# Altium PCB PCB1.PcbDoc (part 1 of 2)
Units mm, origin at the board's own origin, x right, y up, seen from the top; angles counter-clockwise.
Board outline 100 x 100 mm, 2 copper layers (Top Layer, Bottom Layer); 114 components, 82 nets, 496 pads, 121 vias.
Unrouted connection lines stored in the file: 6.
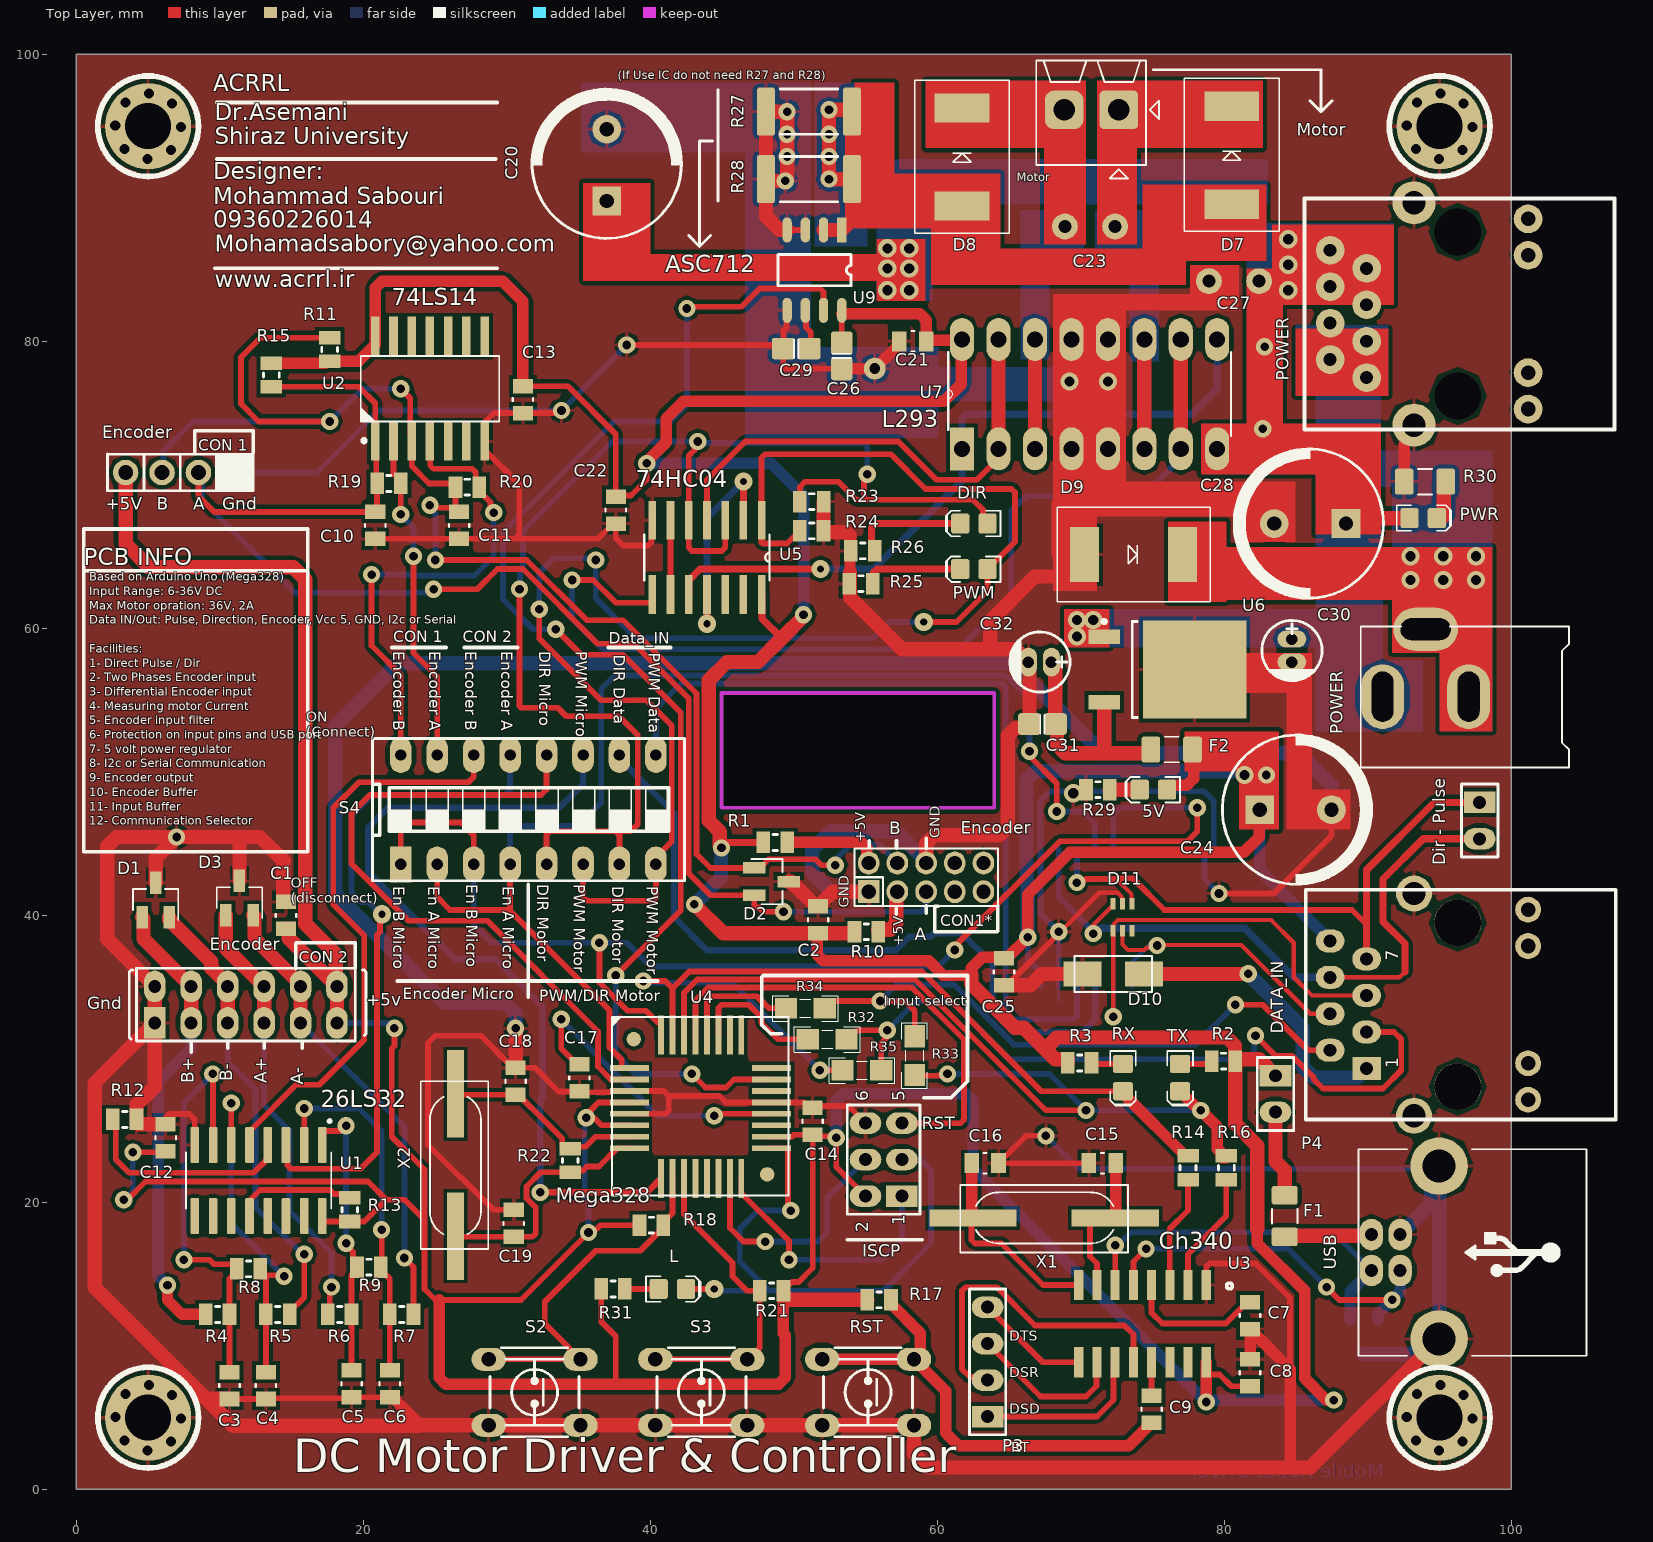
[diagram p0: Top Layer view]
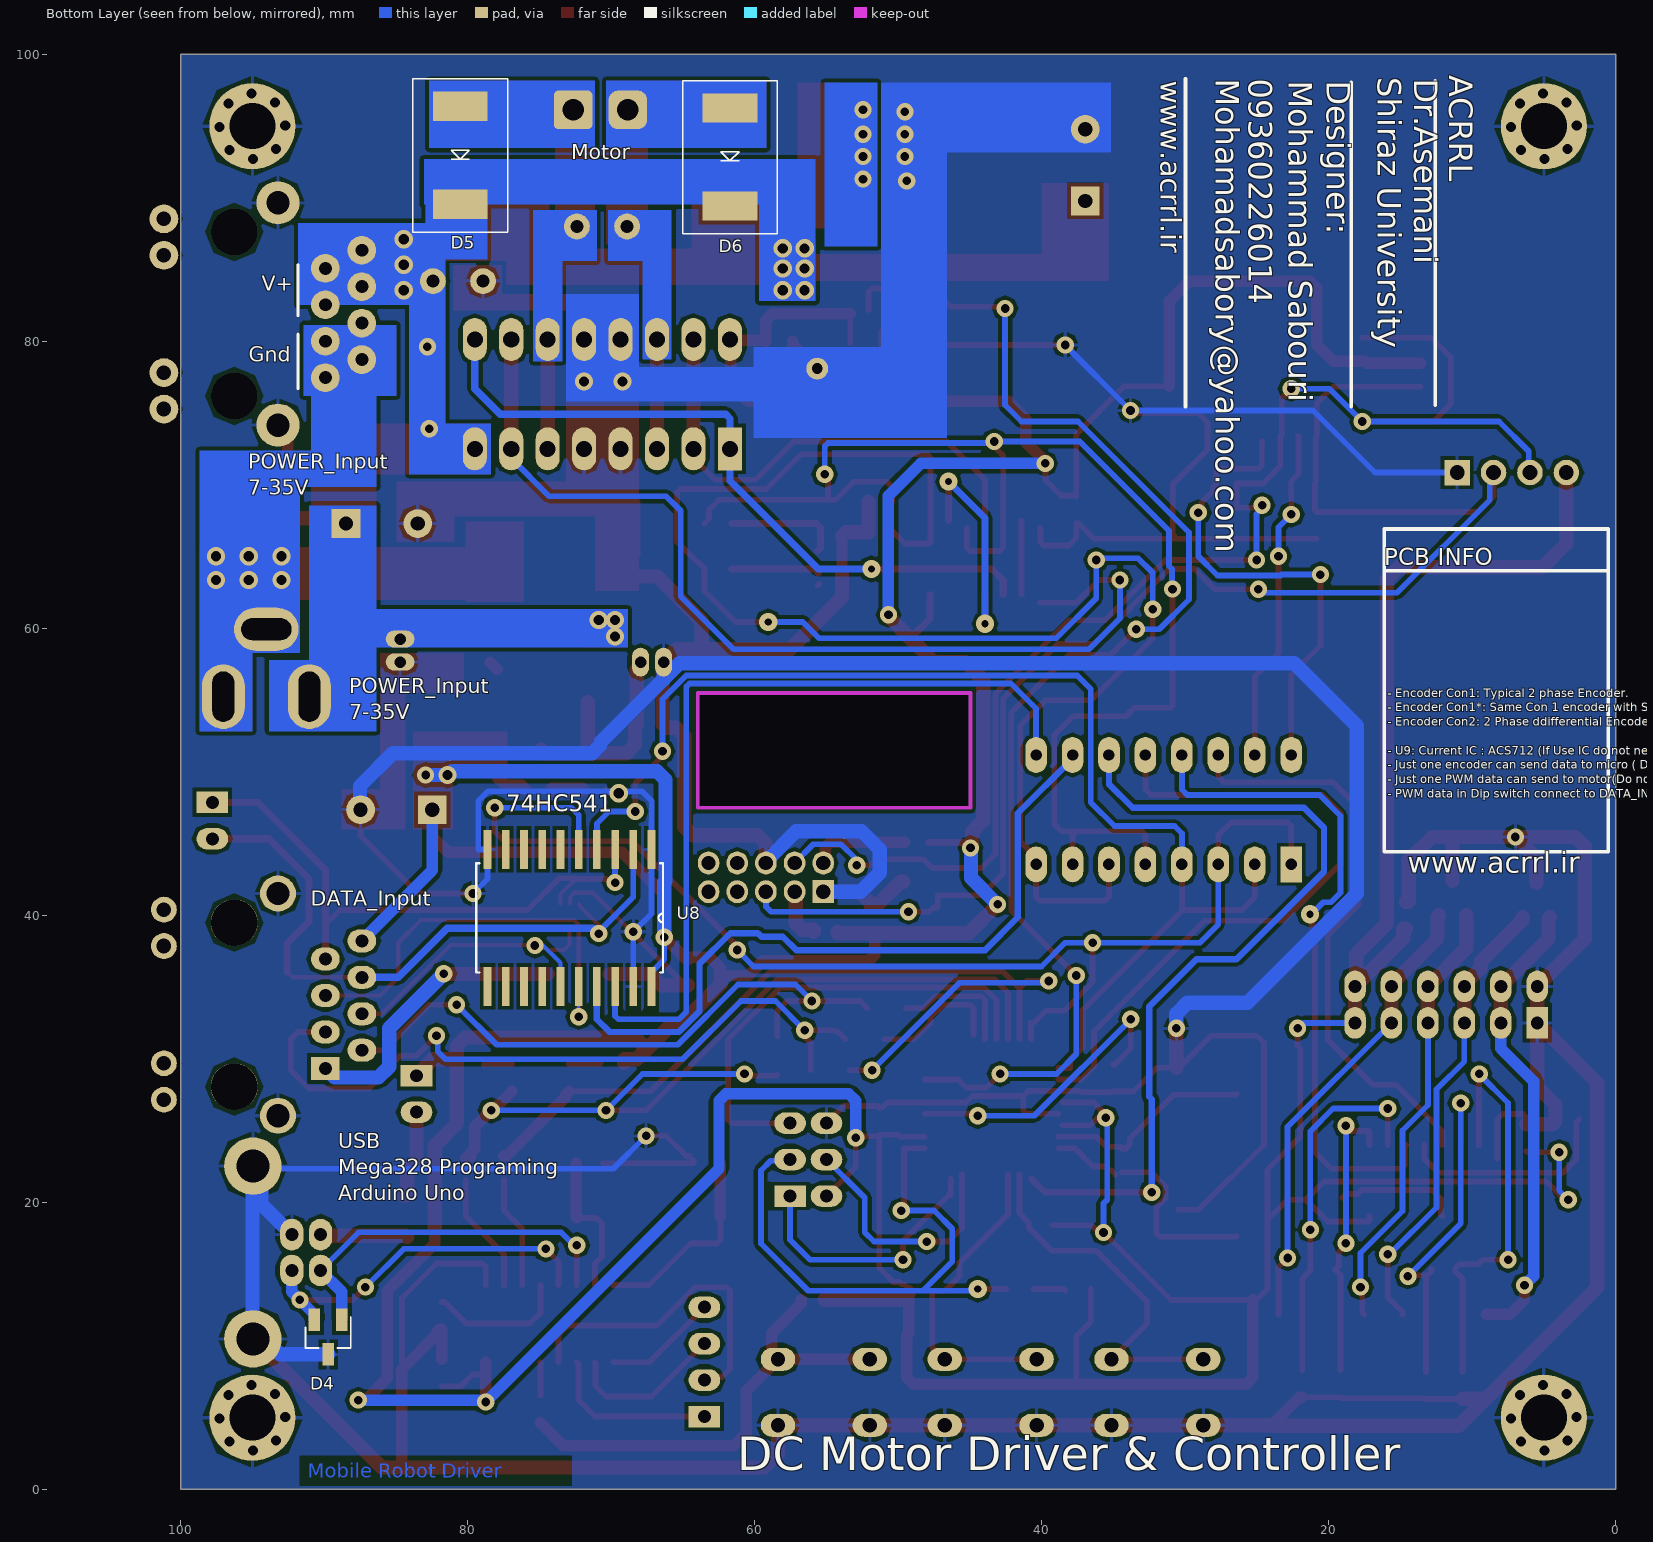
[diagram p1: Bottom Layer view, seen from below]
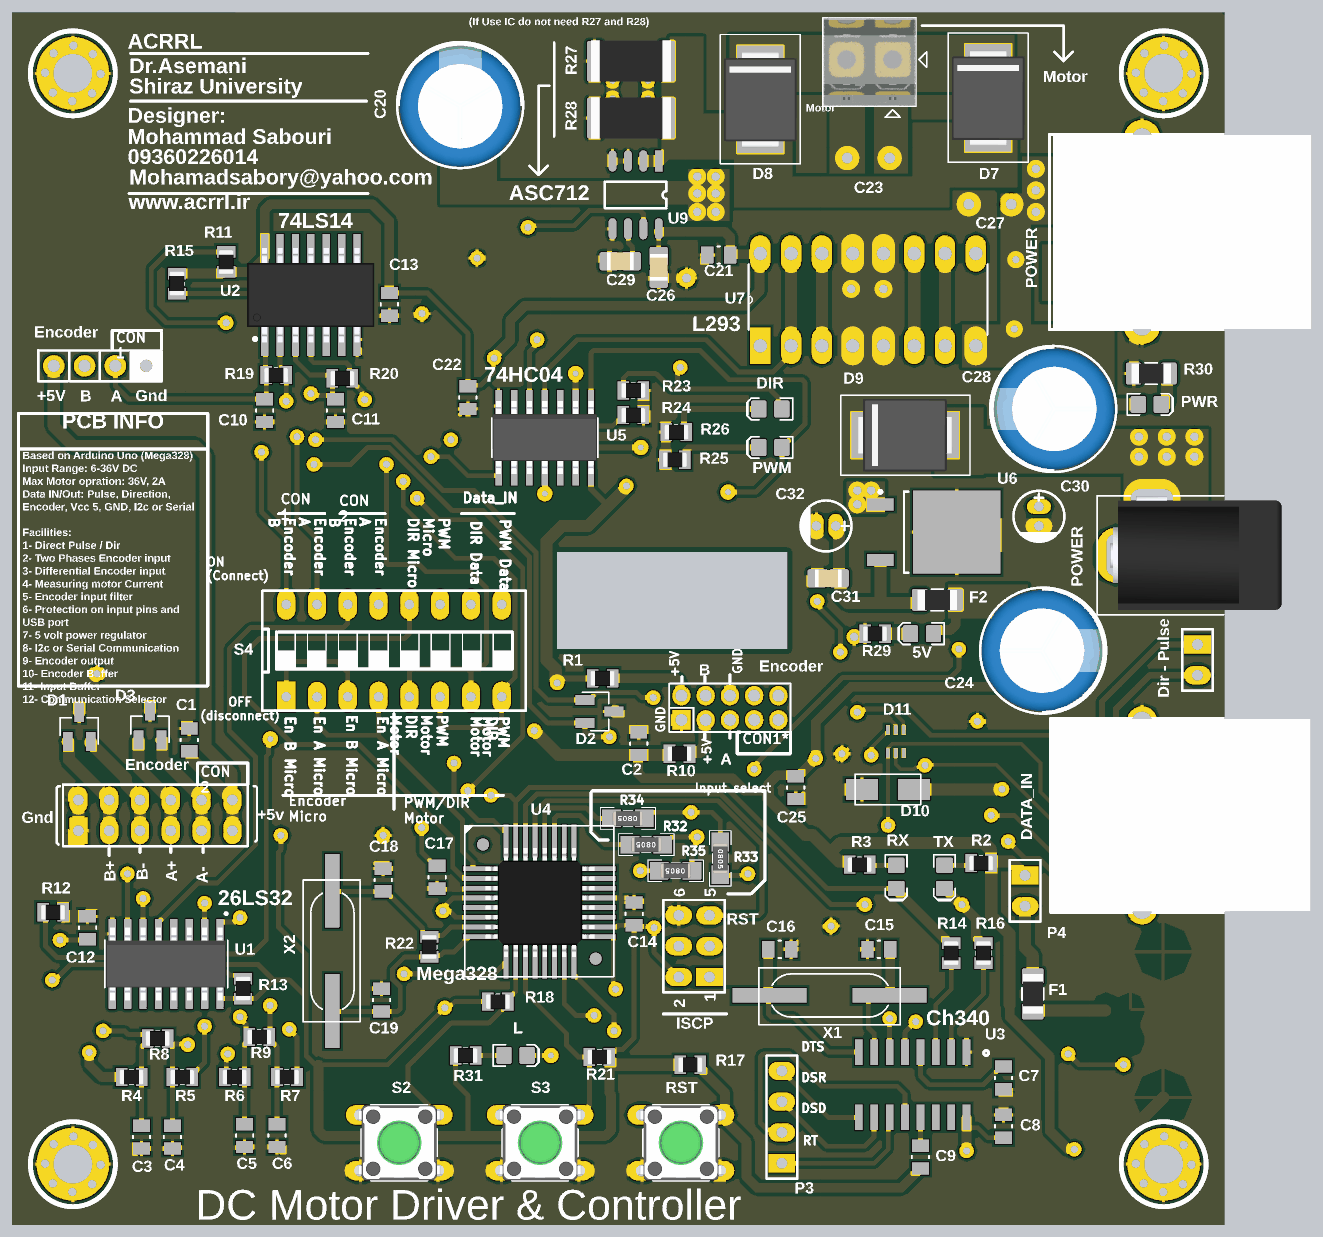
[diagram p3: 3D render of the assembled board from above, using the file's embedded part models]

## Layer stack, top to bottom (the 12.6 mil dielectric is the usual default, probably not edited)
Top Solder: solder mask 0.0102, Solder Resist, Dk 3.5
Top Layer: signal copper 0.0356
Dielectric 1: dielectric 0.32, FR-4, Dk 4.8
Bottom Layer: signal copper 0.0356
Bottom Solder: solder mask 0.0102, Solder Resist, Dk 3.5

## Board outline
0,0 0,100.005 100,100.005 100,0
cut-out: 44.958,55.498 63.958,55.498 63.958,47.498 44.958,47.498

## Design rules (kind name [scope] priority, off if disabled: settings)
Clearance Clearance_3 [InNamedPolygon('GND_L02_P-001')] p1: gap=0.254 ignorepadtopadclearanceinfootprint=FALSE
Clearance Clearance_2 [InNamedPolygon('GND_L02_P-001')] p2: gap=0.254 ignorepadtopadclearanceinfootprint=FALSE
Clearance Clearance_1 [InNamedPolygon('GND_L02_P-001')] p3: gap=0.15 ignorepadtopadclearanceinfootprint=FALSE
Clearance [All] p4: gap=0.15 ignorepadtopadclearanceinfootprint=FALSE
PolygonConnect [All] p1: connectstyle=Relief reliefconductorwidth=0.254 reliefentries=4 polygonreliefangle="90 Angle" airgapwidth=0.254
RoutingVias [All] p1: holewidth=0.8 width=1 viastyle="Through Hole" minholewidth=0.5 minwidth=0.5 maxholewidth=1 maxwidth=1.65
SolderMaskExpansion [All] p1: expansion=0.102 istentingtop=FALSE
Width [All] p1: maxlimit=1 minlimit=0.2 preferedwidth=0.8
30 further rules are at their usual default settings.

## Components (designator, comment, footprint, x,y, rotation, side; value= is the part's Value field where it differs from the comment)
5V "Red" LED-0805-K 75.057,48.768 r180 top
C1 "470nF 50V" 0805 14.605,40.005 r90 top value=470nF
C2 "100nF" 0805 51.689,39.7 r90 top value=470nF
C3 "22pF" 0805 10.668,7.239 r270 top value=470nF
C4 "22pF" 0805 13.208,7.239 r270 top value=470nF
C5 "22pF" 0805 19.177,7.366 r270 top value=470nF
C6 "22pF" 0805 21.844,7.366 r270 top value=470nF
C7 "100nF" 0805 81.788,12.116 r270 top value=470nF
C8 "100nF" 0805 81.788,8.128 r90 top value=470nF
C9 "100nf" 0805 74.93,5.588 r270 top value=470nF
C10 "1uF" 0805 20.828,67.183 r90 top value=470nF
C11 "1uF" 0805 26.67,67.183 r90 top value=470nF
C12 "22pF" 0805 6.223,24.511 r90 top value=470nF
C13 "100nF" 0805 31.115,75.946 r270 top value=470nF
C14 "1uF" 0805 51.308,25.654 r90 top value=470nF
C15 "22pF" 0805 71.501,22.733 r0 top value=470nF
C16 "22pF" 0805 63.322,22.733 r180 top value=470nF
C17 "100nf" 0805 35.052,28.677 r90 top value=470nF
C18 "22pF" 0805 30.607,28.448 r90 top value=470nF
C19 "22pF" 0805 30.48,18.542 r270 top value=470nF
C20 "1000u" "Cap electrolitic radial 10x16-5" 36.957,92.289 r90 top
C21 "470nF 50V" 0805 58.293,80.01 r180 top value=470nF
C22 "22nF 50V" 0805 37.592,68.25 r270 top value=470nF
C23 "100nF" "CAP Ceramic 3.5mm" 72.39,88.011 r180 top
C24 "1000u" "Cap electrolitic radial 10x16-5" 84.963,47.371 r0 top
C25 "470nF 50V" 0805 64.643,36.068 r90 top value=470nF
C26 "approved sub OK" CAPC2012X135N 53.34,78.994 r90 top value=0.1µ
C27 "330pF" "CAP Ceramic 3.5mm" 78.923,84.201 r0 top
C28 "1000u" "Cap electrolitic radial 10x16-5" 85.979,67.31 r180 top
C29 "approved sub OK" CAPC2012X135N 50.165,79.502 r180 top value=1n8
C30 "0.1uF" "cap 00"#1 84.709,58.458 r90 top
C31 "approved sub OK" CAPC2012X135N 67.321,53.34 r180 top value=0.1µ
C32 "0.3uF" "cap 00"#2 67.145,57.658 r0 top
D1 "SM712" PCBComponent_1#1 4.577,39.878 r90 top
D2 "SM712" PCBComponent_1#2 47.244,41.407 r0 top
D3 "SM712" PCBComponent_1#1 10.414,40.005 r90 top
D4 "SM712" PCBComponent_1#2 90.673,11.811 r270 bottom
D5 "SMCJ120CA" DIODE-SMC 80.518,96.893 r90 bottom
D6 "SMCJ120CA" DIODE-SMC 61.722,96.766 r90 bottom
D7 "SMCJ120CA" DIODE-SMC 80.518,89.059 r270 top
D8 "SMCJ120CA" DIODE-SMC 61.722,88.932 r270 top
D9 "SMCJ120CA" DIODE-SMC 69.755,65.151 r180 top
D10 "Diode 1N5819" DO-214AC 72.248,35.918 r0 top
D11 "SMF05C.TCT" SC70-6 72.898,39.878 r180 top
DATA_IN "215877-1 RJ45" HR911105A#1 89.916,29.337 r0 top
DIR "Green" LED-0805-K 62.547,67.31 r180 top
"Dir - Pulse" "Header 2" HDR1X2 97.79,47.879 r270 top (schematic designator "D / P")
Encoder "Encoder" HDR2X6 5.461,32.512 r0 top
Encoder "Encoder motor_AB" hhh 55.214,41.656 r0 top
Encoder "Encoder_Motor" HEADER-1X4 11.049,70.866 r270 top
F1 "Slow-blow" RESC3216X70N 84.201,19.05 r270 top value=500mA
F2 "Slow-blow" RESC3216X70N 76.327,51.562 r0 top value=2A
ISCP "ISP" HDR2X3 57.531,20.447 r90 top
L "L" LED-0805-K 41.529,13.97 r0 top
Motor "Stackable ScrewTerm" 2P_PCB_ScrewTerm_90S_3.81MM 72.644,96.139 r90 top value="2 position"
P3 "Header 4" HDR1X4 63.5,5.08 r90 top
P4 "Header 2" HDR1X2 83.566,28.829 r270 top
POWER "CONN_PWR_JACK_2.1x5.5mm" CONN_PWR_JACK_2.1x5.5mm 104.728,55.245 r270 top value="2.1mm ID, 5.5mm OD"
POWER "215877-1 RJ45" HR911105A#2 96.266,81.915 r270 top
PWM "Green" LED-0805-K 62.547,64.135 r180 top
PWR "Red" LED-0805-K 93.853,67.691 r0 top
R1 "330" "RES 0805 (2012X06L)" 49.529,45.085 r180 top
R2 "1K" "RES 0805 (2012X06L)" 80.771,29.845 r180 top
R3 "1K" "RES 0805 (2012X06L)" 69.089,29.718 r0 top
R4 "1K" "RES 0805 (2012X06L)" 9.017,12.192 r0 top
R5 "1K" "RES 0805 (2012X06L)" 14.859,12.192 r180 top
R6 "1K" "RES 0805 (2012X06L)" 17.527,12.192 r0 top
R7 "1K" "RES 0805 (2012X06L)" 21.845,12.192 r0 top
R8 "120" "RES 0805 (2012X06L)" 12.826,15.367 r180 top
R9 "120" "RES 0805 (2012X06L)" 21.209,15.494 r180 top
R10 "120" "RES 0805 (2012X06L)" 55.879,38.862 r180 top
R11 "10K" "RES 0805 (2012X06L)" 17.653,80.263 r270 top
R12 "R0" "RES 0805 (2012X06L)" 4.19,25.781 r180 top
R13 "R0" "RES 0805 (2012X06L)" 19.05,18.669 r90 top
R14 "1K" "RES 0805 (2012X06L)" 77.47,23.241 r270 top
R15 "10K" "RES 0805 (2012X06L)" 13.589,76.835 r90 top
R16 "1K" "RES 0805 (2012X06L)" 80.137,23.241 r270 top
R17 "10K" "RES 0805 (2012X06L)" 55.118,13.208 r0 top
R18 "10K" "RES 0805 (2012X06L)" 39.243,18.415 r0 top
R19 "10K" "RES 0805 (2012X06L)" 20.955,70.104 r0 top
R20 "10K" "RES 0805 (2012X06L)" 26.416,69.85 r0 top
R21 "10K" "RES 0805 (2012X06L)" 49.275,13.843 r180 top
R22 "1M" "RES 0805 (2012X06L)" 34.417,23.748 r270 top
R23 "10K" "RES 0805 (2012X06L)" 50.42,68.834 r0 top
R24 "10K" "RES 0805 (2012X06L)" 50.419,66.802 r0 top
R25 "330" "RES 0805 (2012X06L)" 55.499,63.119 r180 top
R26 "330" "RES 0805 (2012X06L)" 55.626,65.405 r180 top
R27 "Thick Film" RESC6332X70N 51.054,96.012 r180 top value=R330
R28 "Thick Film" RESC6332X70N 51.054,91.313 r180 top value=R330
R29 "330" "RES 0805 (2012X06L)" 70.359,48.768 r0 top
R30 "Thin Film" RESC3216X70N 93.98,70.231 r180 top value=4.7K
R31 "1K" "RES 0805 (2012X06L)" 36.577,13.97 r0 top
R32 "0" RESC3413X04N 52.324,31.369 r180 top
R33 "0" RESC3413X04N 58.42,30.226 r270 top
R34 "0" RESC3413X04N 50.8,33.528 r180 top
R35 "0" RESC3413X04N 54.737,29.21 r180 top
RST "Switch PB 4Pin" SW_PB_THT_4PIN_SPDT_6X6X7 55.172,6.769 r180 top
RX "RX" LED-0805-K 72.936,28.702 r270 top
S2 "Switch PB 4Pin" SW_PB_THT_4PIN_SPDT_6X6X7 31.931,6.769 r180 top
S3 "Switch PB 4Pin" SW_PB_THT_4PIN_SPDT_6X6X7 43.552,6.769 r180 top
S4 "DIP8" "DIP Switch x8" 22.606,43.561 r0 top
TX "TX" LED-0805-K 76.915,28.702 r270 top
U1 "AM26LS32ACD" SOIC127P600X175-16N 12.7,21.525 r270 top
U2 "SN74LS14DR" SOIC127P780X200-14N 24.638,76.708 r90 top
U3 "CH340G" CH340G 74.295,11.557 r180 top
U4 "ATMEGA328" QFP32 38.842,29.371 r0 top
U5 "74HC04D,653" SOIC127P600X175-14N 43.942,64.948 r270 top
U6 "L7805CD2T-TR" TO252-3M 76.028,57.144 r180 top
U7 "L293N" DIP254P762X508-16 79.502,80.137 r90 top
U8 "74HC541D" SOIC127P1032X265-20N 72.898,39.827 r270 bottom
U9 "ACS712" SOIC8 53.34,87.769 r270 top
USB "USB-B" USB_TypeB_Tyco 105.241,16.51 r180 top
X1 "12MC" XTAL-RU49/4 72.39,18.923 r180 top
X2 "16MC" XTAL-RU49/4 26.416,17.653 r90 top

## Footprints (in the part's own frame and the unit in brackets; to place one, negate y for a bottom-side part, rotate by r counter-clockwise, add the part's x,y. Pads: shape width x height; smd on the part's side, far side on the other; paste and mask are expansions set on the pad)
2P_PCB_ScrewTerm_90S_3.81MM [mm] "TERM BLOCK 2POS SIDE ENT STACKABLE 3.81MM"
  rrect50% 2.7x2.7 hole 1.5: 2(0,3.81)
  rrect25% 2.7x2.7 hole 1.5: F(0,0)
  silkscreen extent -4.78,-2.79 3.45,5.75, body extent -3.85,-1.91 3.45,5.71, height 8.5
0805 [mil]
  rect 40x55 smd: 1(-37,0) 2(37,0)
  silkscreen extent -4,-28 4,28, body extent -47,-28 47,28, height 24
"cap 00"#1 [mm]
  oval 1.2x2 hole 0.8: 1(0.8,0) F(-0.8,0)
  silkscreen extent -2.1,-2.1 2.1,2.1
"cap 00"#2 [mm]
  oval 1.2x2 hole 0.8: 1(0.8,0) 2(-0.8,0)
  silkscreen extent -2.1,-2.1 2.1,2.1
"CAP Ceramic 3.5mm" [mm] "Bipolar Capacitor-Design:Ali Hafizi"
  round 1.8 hole 0.9: 1(0,0) 2(3.5,0)
"Cap electrolitic radial 10x16-5" [mm] "Cap electrolitic radial 10x16-5-Design:Abbas Basereh"
  rect 2x2 hole 1: 1(-2.5,0)
  round 2 hole 1: 2(2.5,0)
  silkscreen extent -5.1,-5.2 5.3,5.2, body extent -5,-5 5,5, height 16
CAPC2012X135N [mm] "Chip Capacitor, Body 2.0x1.2mm, EIA 0805, IPC Medium Density"
  round 0.254 on Mech15: 0(0,0)
  rrect25% 1.6x1.5 smd: 1(-0.9,0) 2(0.9,0)
  Top Layer pour cut-out: -0.675,0.7 -0.475,0.9 0.475,0.9 0.675,0.7 0.675,-0.7 0.475,-0.9 -0.475,-0.9 -0.675,-0.7
  silkscreen extent -0.15,-0.65 0.15,0.65, body extent -1.1,-0.72 1.1,0.73, height 1.34
CH340G [mm]
  rect 0.635x2.1 smd: 1(-4.445,-2.695) 2(-3.175,-2.695) 3(-1.905,-2.695) 4(-0.635,-2.695) 5(0.635,-2.695) 6(1.905,-2.695) 7(3.175,-2.695) 8(4.445,-2.695) 9(4.445,2.695) 10(3.175,2.695) 11(1.905,2.695) 12(0.635,2.695) 13(-0.635,2.695) 14(-1.905,2.695) 15(-3.175,2.695) 16(-4.445,2.695)
  silkscreen extent -6.26,-2.82 -5.86,-2.42, body extent -4.97,-3.11 5.01,3.13, height 1.58
CONN_PWR_JACK_2.1x5.5mm [mm] "Power Connector, 2.1mm ID, 5.5mm OD"
  oval 4.5x3 hole 1.511 slot 3.5 at 0 deg: 1(0,-13.7) 2(0,-7.7)
  oval 3x4.5 hole 1.511 slot 3.5 at 90 deg: 3(-4.7,-10.7)
  silkscreen extent -4.9,-15.22 4.92,-0.7, body extent -4.9,-14.1 4.5,0, height 11
DIODE-SMC [mil]
  rect 80x150 smd: A(-19.69,0) K(-288.74,0)
  silkscreen extent -365,-130 55,130, body extent -309,-118 2,118, height 84
DIP254P762X508-16 [mil]
  rect 118.11x66 hole 44: 1(-300,700)
  oval 118.11x66 hole 44: 2(-300,600) 3(-300,500) 4(-300,400) 5(-300,300) 6(-300,200) 7(-300,100) 8(-300,0) 9(0,0) 10(0,100) 11(0,200) 12(0,300) 13(0,400) 14(0,500) 15(0,600) 16(0,700)
  silkscreen extent -265,-38 -35,738
"DIP Switch x8" [mm] "Switch DIP 8 way flat slide Thru-Hole-Design:Ali Hafizi"
  rect 1.5x2.5 hole 0.8: 1(0,0)
  oval 1.5x2.5 hole 0.8: 2(2.54,-0.01) 3(5.08,0) 4(7.62,0) 5(10.16,0) 6(12.7,0) 7(15.24,0) 8(17.78,0) 9(17.78,7.62) 10(15.24,7.62) 11(12.7,7.62) 12(10.16,7.62) 13(7.62,7.62) 14(5.08,7.62) 15(2.54,7.62) 16(0,7.62)
  silkscreen extent -1.98,-1.14 19.76,8.76, body extent -1.98,-1.14 19.76,8.76, height 6.35
DO-214AC [mm]
  rect 2.65x1.75 smd: A(-2.15,0) C(2.15,0)
  silkscreen extent -2.7,-1.25 2.7,1.25
HDR1X2 [mm] "Connector; Header; 2 Position"
  rect 1.5x2.2 hole 0.9: 1(0,0)
  oval 1.5x2.2 hole 0.9: 2(2.54,0)
  silkscreen extent -1.27,-1.27 3.81,1.27
HDR1X4 [mm] "Connector; Header; 4 Position"
  rect 1.5x2.2 hole 0.9: 1(0,0)
  oval 1.5x2.2 hole 0.9: 2(2.54,0) 3(5.08,0) 4(7.62,0)
  silkscreen extent -1.27,-1.27 8.89,1.27
HDR2X3 [mm] "Connector; Header; 3x2 Position"
  rect 1.5x2.2 hole 0.9: 1(0,0)
  oval 1.5x2.2 hole 0.9: 2(0,2.54) 3(2.54,0) 4(2.54,2.54) 5(5.08,0) 6(5.08,2.54)
  silkscreen extent -1.27,-1.27 6.35,3.81
HDR2X6 [mm] "Connector; Header; 6x2 Position"
  rect 1.5x2.2 hole 0.9: 1(0,0)
  oval 1.5x2.2 hole 0.9: 2(0,2.54) 3(2.54,0) 4(2.54,2.54) 5(5.08,0) 6(5.08,2.54) 7(7.62,0) 8(7.62,2.54) 9(10.16,0) 10(10.16,2.54) 11(12.7,0) 12(12.7,2.54)
  silkscreen extent -1.27,-1.27 13.97,3.81
HEADER-1X4 [mil]
  rect 70x70 hole 40: 1(0,0)
  round 70 hole 40: 2(0,-100) 3(0,-200) 4(0,-300)
  silkscreen extent -51,-350 50,50, body extent -50,-350 50,50, height 470
hhh [mm]
  rect 1.5x1.6 hole 1: 1(0,0)
  oval 1.5x1.6 hole 1: 2(0,2) 3(2,0) 4(2,2) 5(4,0) 6(4,2) 7(6,0) 8(6,2) 9(8,0) 10(8,2)
  silkscreen extent -1,-1 9,3
HR911105A#1 [mm] "HR911105A"
  rect 2x1.6 hole 0.9: 1(0,0)
  oval 2x1.6 hole 0.9: 2(-2.54,1.27) 3(0,2.54) 4(-2.54,3.81) 5(0,5.08) 6(-2.54,6.35) 7(0,7.62) 8(-2.54,8.89)
  round 1.8 hole 1.02: 9(11.25,-2.18) 10(11.25,0.36) 11(11.25,8.53) 12(11.25,11.07)
  round 2.5 hole 1.63: 13(3.3,12.19) 14(3.3,-3.3)
  round 3.25 hole 3.25 unplated: C(6.35,10.16) D(6.35,-1.27)
  silkscreen extent -4.23,-3.55 17.35,12.45, body extent -4.19,-3.49 17.21,12.39, height 13.5
HR911105A#2 [mm] "Single Port RJ45 Connector with Integrated Magnetics and LED for 10/100Base-T NIC Applications"
  round 3 hole 1.63: 0(7.745,-3.05) 1(-7.745,-3.05)
  round 2 hole 0.9: 1(4.44,-6.35) 2(3.18,-8.89) 3(1.9,-6.35) 4(0.64,-8.89) 5(-0.64,-6.35) 6(-1.9,-8.89) 7(-3.18,-6.35) 8(-4.44,-8.89)
  round 2 hole 1.02: 9(6.625,4.9) 10(4.085,4.9) 11(-4.085,4.9) 12(-6.625,4.9)
  round 0 hole 3.25: 13(-5.715,0) 13(5.715,0)
  Top Layer pour cut-out: -5.715,1.8 -5.026,1.663 -4.442,1.273 -4.052,0.689 -3.915,0 -3.915,0 -4.052,-0.689 -4.442,-1.273 -5.026,-1.663 -5.715,-1.8 -5.715,-1.8 -5.715,-1.8 -6.404,-1.663 -6.988,-1.273 -7.378,-0.689 -7.515,0 -7.515,0 -7.378,0.689 -6.988,1.273 -6.404,1.663 -5.715,1.8 -5.715,1.8
  Top Layer pour cut-out: 5.715,1.8 6.404,1.663 6.988,1.273 7.378,0.689 7.515,0 7.515,0 7.378,-0.689 6.988,-1.273 6.404,-1.663 5.715,-1.8 5.715,-1.8 5.715,-1.8 5.026,-1.663 4.442,-1.273 4.052,-0.689 3.915,0 3.915,0 4.052,0.689 4.442,1.273 5.026,1.663 5.715,1.8 5.715,1.8
  Bottom Layer pour cut-out: -5.715,1.8 -5.026,1.663 -4.442,1.273 -4.052,0.689 -3.915,0 -3.915,0 -4.052,-0.689 -4.442,-1.273 -5.026,-1.663 -5.715,-1.8 -5.715,-1.8 -5.715,-1.8 -6.404,-1.663 -6.988,-1.273 -7.378,-0.689 -7.515,0 -7.515,0 -7.378,0.689 -6.988,1.273 -6.404,1.663 -5.715,1.8 -5.715,1.8
  Bottom Layer pour cut-out: 5.715,1.8 6.404,1.663 6.988,1.273 7.378,0.689 7.515,0 7.515,0 7.378,-0.689 6.988,-1.273 6.404,-1.663 5.715,-1.8 5.715,-1.8 5.715,-1.8 5.026,-1.663 4.442,-1.273 4.052,-0.689 3.915,0 3.915,0 4.052,0.689 4.442,1.273 5.026,1.663 5.715,1.8 5.715,1.8
  silkscreen extent -8.05,-10.68 8.05,10.92, body extent -8,-10.38 8,10.92, height 2.3
LED-0805-K [mil]
  round 20 on Mech15: 0(0,0)
  rrect25% 50x55.12 smd: A(-37.5,0) K(37.5,0)
  Top Layer pour cut-out: -15,30 15,30 15,-30 -15,-30
  silkscreen extent -72,-35 77,35, body extent -39,-25 39,25, height 31
PCBComponent_1#1 [mil]
  rect 61.42x31.5 smd: 1(0,-74.8) 2(0,0) 3(94.48,-37.4)
  silkscreen extent -8,-100 77,25
PCBComponent_1#2 [mil]
  rect 61.42x31.5 smd: 1(0,74.8) 2(0,0) 3(94.48,37.4)
  silkscreen extent -8,-25 77,100
QFP32 [mm]
  rect 2.7x0.4 smd: 1(-0.3,0) 2(-0.3,-0.8) 3(-0.3,-1.6) 4(-0.3,-2.4) 5(-0.3,-3.2) 6(-0.3,-4) 7(-0.3,-4.8) 8(-0.3,-5.6) 17(9.6,-5.6) 18(9.6,-4.8) 19(9.6,-4) 20(9.6,-3.2) 21(9.6,-2.4) 22(9.6,-1.6) 23(9.6,-0.8) 24(9.6,0)
  rect 0.4x2.7 smd: 9(1.9,-7.7) 10(2.7,-7.7) 11(3.5,-7.7) 12(4.3,-7.7) 13(5.1,-7.7) 14(5.9,-7.7) 15(6.7,-7.7) 16(7.5,-7.7) 25(7.5,2.3) 26(6.7,2.3) 27(5.9,2.3) 28(5.1,2.3) 29(4.3,2.3) 30(3.5,2.3) 31(2.7,2.3) 32(1.9,2.3)
  round 1 smd: F1(0,2.007) F2(9.296,-7.417)
  silkscreen extent -1.52,-8.89 10.79,3.56, body extent 0.2,-7.29 9.2,1.71, height 1.4
"RES 0805 (2012X06L)" [mm] "Chip Resistor, 2-Leads, Body 2.0x1.3mm, IPC High Density _ (0.100 W)"
  rect 0.95x1.5 smd: 1(0,0) 2(1.65,0)
  silkscreen extent 0.67,-0.55 0.97,0.55, body extent -0.19,-0.63 1.84,0.64, height 0.6
RESC3216X70N [mm] "Chip Resistor, Body 3.2x1.6mm, EIA 1206, IPC Medium Density"
  round 0.508 on Mech15: 0(0,0)
  rrect25% 1.3x1.8 smd: 1(-1.45,0) 2(1.45,0)
  silkscreen extent -0.51,-0.89 0.51,0.89, body extent -1.62,-0.82 1.63,0.83, height 0.69
RESC3413X04N [mm] "Chip Resistor, 2-Leads, Body 3/40x1/30mm, IPC Medium Density-Design:Abbas Basereh"
  rect 1.55x1.45 smd: 1(-1.35,0) 2(1.35,0)
  silkscreen extent -2.29,-0.89 2.29,0.89, body extent -1.25,-0.62 1.25,0.62, height 0.79
RESC6332X70N [mm] "Chip Resistor, Body 6.3x3.2mm, 2512, IPC Medium Density"
  round 1 on Mech15: 0(0,0)
  rrect25% 1.25x3.35 smd: 1(-3,0) 2(3,0)
  silkscreen extent -2,-1.58 2,1.58, body extent -3.3,-1.7 3.3,1.7, height 0.69
SC70-6 [mm]
  rect 0.35x0.8 smd paste-1 mask+0: 1(-0.65,-0.95) 2(0,-0.95) 3(0.65,-0.95) 4(0.65,0.95) 5(0,0.95) 6(-0.65,0.95)
SOIC8 [mm]
  rect 1.75x0.65 smd: 1(0,0)
  oval 1.75x0.65 smd: 2(0,-1.27) 3(0,-2.54) 4(0,-3.81) 5(5.6,-3.81) 6(5.6,-2.54) 7(5.6,-1.27) 8(5.6,0)
  silkscreen extent 1.71,-4.44 3.89,0.64
SOIC127P600X175-14N [mil]
  rect 106.3x21 smd: 1(-102,150) 2(-102,100) 3(-102,50) 4(-102,0) 5(-102,-50) 6(-102,-100) 7(-102,-150) 8(102,-150) 9(102,-100) 10(102,-50) 11(102,0) 12(102,50) 13(102,100) 14(102,150)
  silkscreen extent -63,-172 63,172, body extent -118,-170 118,170, height 69
SOIC127P600X175-16N [mm]
  rrect25% 2.5x0.6 smd: 1(-2.475,4.445) 2(-2.475,3.175) 3(-2.475,1.905) 4(-2.475,0.635) 5(-2.475,-0.635) 6(-2.475,-1.905) 7(-2.475,-3.175) 8(-2.475,-4.445) 9(2.475,-4.445) 10(2.475,-3.175) 11(2.475,-1.905) 12(2.475,-0.635) 13(2.475,0.635) 14(2.475,1.905) 15(2.475,3.175) 16(2.475,4.445)
  silkscreen extent -4.24,-5.06 1.95,5.06, body extent -3,-4.95 3,4.95, height 1.75
SOIC127P780X200-14N [mm] "SOIC, 14 Leads, Body 10.5x5.3mm, Pitch 1.27mm, IPC Medium Density"
  round 1 on Mech15: 0(0,0)
  rect 2.7x0.6 smd: 1(-3.67,3.81) 2(-3.67,2.54) 3(-3.67,1.27) 4(-3.67,0) 5(-3.67,-1.27) 6(-3.67,-2.54) 7(-3.67,-3.81) 8(3.67,-3.81) 9(3.67,-2.54) 10(3.67,-1.27) 11(3.67,0) 12(3.67,1.27) 13(3.67,2.54) 14(3.67,3.81)
  silkscreen extent -3.75,-4.83 2.29,4.83, body extent -3.9,-5.25 3.9,5.25, height 2
SOIC127P1032X265-20N [mil]
  rect 106.3x21 smd: 1(-188,225) 2(-188,175) 3(-188,125) 4(-188,75) 5(-188,25) 6(-188,-25) 7(-188,-75) 8(-188,-125) 9(-188,-175) 10(-188,-225) 11(188,-225) 12(188,-175) 13(188,-125) 14(188,-75) 15(188,-25) 16(188,25) 17(188,75) 18(188,125) 19(188,175) 20(188,225)
  silkscreen extent -150,-256 150,256
SW_PB_THT_4PIN_SPDT_6X6X7 [mm] "SWITCH, PUSHBUTTON, THD, SPDT, 6X6X7.0 mm Height ; 1,000,000 cycles ; 0.98N Force, SKHHBVA010"
  oval 2.4x1.6 hole 1 mask+0.1: 1(-3.2,2.3) 2(-3.2,-2.3) 3(3.2,-2.3) 4(3.2,2.3)
  silkscreen extent -3.1,-3.1 3.1,3.1, body extent -3.95,-3.1 3.95,3.1, height 7.03
TO252-3M [mm] "D-PAK, 4-Leads, Body 6.1x6.5mm, Pitch 2.28mm, Lead Span 9.7mm, IPC Low Density"
  rect 2.2x1 smd: 1(4.4,-2.28) 3(4.4,2.28)
  rect 7.2x6.85 smd: 2(-1.9,0)
  silkscreen extent 2.1,-3.45 4.52,3.35, body extent -3.75,-3.35 2.45,3.35, height 2.38
USB_TypeB_Tyco [mm]
  oval 1.626x2.2 hole 0.9: 1(14.99,-1.25) 2(14.99,1.25) 3(12.99,1.25) 4(12.99,-1.25)
  round 4 hole 2.3: MH(10.28,6.02) MH(10.28,-6.02)
  silkscreen extent 0,-7.2 15.9,7.2, body extent 0,-7.19 15.7,7.19, height 11.5
XTAL-RU49/4 [mil]
  rect 240x47.24 smd: 1(0,0) 2(390,0)
  silkscreen extent -35,-90 425,95, body extent -78,-90 468,95, height 120

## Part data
5V PWR: library part LED_SMD_Red_0805_6mcd, "LED 0805 SMD Red 6mcd 621nm", Manufacturer 1="Lite-On Inc", Manufacturer Part Number 1=LTST-C171EKT, Package / Case=0805, Ratings="6 mcd; 621 nm", Supplier Part Number 1=160-1422-1-ND
C1 C2 C3 C4 C5 C6 C7 C8 C9 C10 C11 C12 C13 C14 C15 C16 C17 C18 C19 C21 C22 C25: library part "CAP 470nF 50V", "CAP CER 0.1UF 50V X7R 0805", Package=0805, Rating=50V, Tolerance=10%
C20 C24 C28: library part "CAP POL 1000uF TH", "NICHICON   UVR1E102MPD1TD   ALUMINUM ELECTROLYTIC CAPACITOR, 1000UF, 25V, 20%, RADIAL, FULL REEL", Capacitance=1mF, Case/Package=Radial, Dielectric Material=Aluminium, Leakage Current=750uA, Manufacturer=Nichicon, Manufacturer Part Number=UVR1E102MPD1TD, Max Operating Temperature=85°C, Min Operating Temperature=-40°C, Package Quantity=500, Ripple Current=960mA, Supplier Part Number 1=493-5913-1-ND, Tolerance=20%, Voltage=25V
C23 C27: library part "CAP CERAMIC TOTAL SIZE", "CAP Ceramic Total"
C26 C31: library part CAPC_1u_0805_X7R_16V_10%, "Capacitor SMD Cer 1uF 10% 16V X7R 0805", Manufacturer 1=Yageo, Manufacturer 2=Kemet, Manufacturer 3="Samsung Electro-Mechanics America, Inc", Manufacturer 4="TDK Corporation", Manufacturer Part Number 1=CC0805KKX7R7BB105, Manufacturer Part Number 2=C0805C105K4RACTU, Manufacturer Part Number 3=CL21B105KOFNNNE, Manufacturer Part Number 4=C2012X7R1C105K125AA, Package / Case="0805 (2012 metric)", Ratings="16V; X7R", Supplier Part Number 1=311-1365-6-ND, Temperature Coefficient=X7R, Tolerance=±10%
C29: library part CAPC_1n8_50V_0805, "Capacitor SMD Cer 1.8nF 10% 50V X7R 0805", Manufacturer 1="AVX Corporation", Manufacturer Part Number 1=08055C182KAT2A, Operating Temperature="-55°C ~ 125°C", Package / Case="0805 (2012 metric)", Ratings="50V; X7R", Supplier Part Number 1=478-1374-1-ND, Tolerance=±10%
C30 C32: library part Cap-Polar, "Polar Capacitor", Voltage=35V
D1 D2 D3 D4: library part SM712.TC, "Asymmetrical TVS Diode for  Extended Common-Mode RS-485", Manufacturer=SEMTECH, Operating Temp="-55 to 125 °C", Storage Temp="-55 to 150 °C"
D5 D6 D7 D8 D9: "Transient Surpression Diode TVS", Supplier Part Number 1=SMCJ120CABTR-ND
D10: "SS14"
D11: "12.5V Clamp 8A _8/20Âµs_ Ipp Tvs Diode Surface Mount SC-70-6", Package="SOT-363 Diodes Inc."
DATA_IN POWER: "Female Header, Pitch 2.54 mm, 2 x 4 Position, Height 11.5 mm, Tail Length 3 mm, -40 to 105 degC, RoHS, Tape and Reel", LED Color="Does Not Contain LED", Ratings=Cat3, Standard Package=1, Supplier Part Number 1=A105009TR-ND
DIR L PWM RX TX: library part LED_SMD_Green_0805_6mcd, "LED, 0805 SMD, Green", Manufacturer 1=LITE-ON, Manufacturer Part Number 1=LTST-C171GKT, Package / Case=0805, Ratings="6 mcd; 569 nm", Supplier Part Number 1=160-1423-1-ND
"Dir - Pulse" P4: "Header, 2-Pin"
Encoder: library part "Header 6X2", "Header, 6-Pin, Dual row"
Encoder: library part "Header 5X2", "Header, 5-Pin, Dual row"
Encoder: library part HEADER-1X4, Supplier Part Number 1=S1011E-36-ND
F1 F2: library part FUSE_160mA_1206, "Fuse 160mA 63VDC 1206 SMD", Manufacturer 1="Holly Fuse", Manufacturer Part Number 1=12T-0160L, Package / Case="1206 (3216 metric)", Ratings="160mA; 63VDC; slow-blow"
ISCP: library part "Header 3X2", "Header, 3-Pin, Dual row"
Motor: library part 2P_ScrewTerm_90S_3.81MM, "Terminal Block Screw Type THT 2-Position 3.81mm pitch", Color=Black, Manufacturer 1="Tyco Electronics", Manufacturer Part Number 1=1776113-2, Package / Case="Side Entry; 3.81mm pitch", Supplier Part Number 1=Motor
P3: "Header, 4-Pin"
POWER: "Power Connector, THT, 2.1mm ID, 5.5mm OD", Manufacturer 1="CUI Inc", Manufacturer Part Number 1=PJ-102AH, Package / Case="PCB mount", Supplier Part Number 1=CP-102AH-ND
R1 R2 R3 R4 R5 R6 R7 R8 R9 R10 R11 R12 R13 R14 R15 R16 R17 R18 R19 R20 R21 R22 R23 R24 R25 R26 R29 R31: library part Resistor, "Resistor", Power="1/8 W", Tolerance=5%
R27 R28: library part RES_3K3_2512_5%, "Resistor SMD chip 3.3k Ohm 1W 5% 2512", Manufacturer 1=Vishay/Dale, Manufacturer Part Number 1=CRCW25123K30JNEG, Package / Case="2512 (6332 metric)", Ratings=1W, Supplier Part Number 1=541-3.3KXCT-ND, Tolerance=±5%
R30: library part RES_91R_1206_5%, "Resistor SMD chip 91 Ohm 0.25W 5% 1206", Manufacturer 1=Yageo, Manufacturer Part Number 1=RC1206JR-0791RL, Package / Case="1206 (3216 Metric)", Ratings="1/4 W", Supplier Part Number 1=311-91ERCT-ND, Tolerance=±5%
R32 R33 R34 R35: library part "RES 0805 0.125W", "RES 0805"
RST S2 S3: library part SW-PB-4Pin, "Switch Push Button 4 Pin"
S4: library part "DIP Switch 8", "8 BIT DIP Switch"
U1: "Quadruple Differential Line Receivers 16-SOIC 0 to 70", Package="SOIC-16 Texas Instruments"
U2: Package=None
U4: library part ATMEGA328-TQFP32, "ATMEGA328 - TQFP", Supplier Part Number 1=ATMEGA328-AU-ND
U5: "Inverter IC 6 Channel 14-SO", Package="SO14-14 Nexperia USA Inc."
U7: "Bipolar Motor Driver Bipolar Parallel 16-PDIP", Package="PDIP-16 Texas Instruments"
U8: "Buffer, Non-Inverting 1 Element 8 Bit per Element 3-State Output 20-SOIC", Package="SOIC-20 Toshiba"
USB: library part USB_TypeB, "Connector THT Type B USB connector", Manufacturer 1="TE Connectivity", Manufacturer Part Number 1=292304-1, Package / Case="R/A Type B", Supplier Part Number 1=A31725-ND
X1 X2: library part 16MC-HC49US, "16MHZ CRSYTAL HC49US", Supplier Part Number 1=815-ABLS-16.0M-T

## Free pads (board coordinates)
  round 6 hole 3.2: 2(5,95) 2(95,5) 2(95,95) ""(5.005,5)
  round 1.524 hole 0.762: 14(55.639,78.105)
  round 0 hole 0.7: 26(4.953,92.71) 26(4.958,2.71) 26(94.953,2.71) 26(94.953,92.71) 27(6.586,93.347) 27(6.591,3.347) 27(96.586,3.347) 27(96.586,93.347) 28(7.29,94.953) 28(7.295,4.953) 28(97.29,4.953) 28(97.29,94.953) 29(6.653,96.586) 29(6.658,6.586) 29(96.653,6.586) 29(96.653,96.586) 30(5.047,97.29) 30(5.052,7.29) 30(95.047,7.29) 30(95.047,97.29) 31(3.414,96.653) 31(3.419,6.653) 31(93.414,6.653) 31(93.414,96.653) 32(2.71,95.047) 32(2.715,5.047) 32(92.71,5.047) 32(92.71,95.047) 33(3.347,93.414) 33(3.352,3.414) 33(93.347,3.414) 33(93.347,93.414) 34(4.958,2.71) 34(94.953,2.71) 35(6.591,3.347) 35(96.586,3.347)
  round 4.5 hole 3.2: ""(5.005,5)

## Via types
v1: diameter 1.2, hole 0.6, Top Layer to Bottom Layer, 93 vias
v2: diameter 1.27, hole 0.711, Top Layer to Bottom Layer, 22 vias
v3: diameter 1.27, hole 0.5, Top Layer to Bottom Layer, 6 vias

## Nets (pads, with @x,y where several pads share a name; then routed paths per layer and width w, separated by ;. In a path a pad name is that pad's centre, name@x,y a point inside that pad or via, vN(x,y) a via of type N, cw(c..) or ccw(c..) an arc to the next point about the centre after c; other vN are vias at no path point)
1: C1.2 C2.2 C3.2 C4.2 C5.2 C6.2 C7.2 C8.2 C10.1 C11.1 C12.2 C13.2 C14.2 C15.1 C16.1 C17.1 C18.2 C19.1 C20.2 C21.2 C22.2 C24.2 C25.1 C26.1 C27.1 C28.2 C29.2 C30.F C31.2 C32.2 D1.3 D2.3 D3.3 D4.3 D9.A D10.A D11.2 DATA_IN.13 DATA_IN.14 Encoder.1 Encoder.2@5.461,35.052 Encoder.6@59.214,43.656 ISCP.6 pad. pad.2 pad.14 pad.26 pad.27 pad.28 pad.29 pad.30 pad.31 pad.32 pad.33 pad.34 pad.35 POWER.0 POWER.1@93.216,89.66 R12.1 R23.2 R24.2 R25.2 R26.2 R27.2 R28.2 R29.1 R30.2 RST.1 RST.4 S2.1 S2.4 S3.1 S3.4 U1.8 U2.7 U3.1 U4.3 U4.5 U4.21 U5.7 U6.2 U7.4 U7.5 U7.12 U7.13 U8.1 U8.10 U8.19 U9.3 U9.4 U9.5 USB.4 USB.MH | length 730.2
  Top Layer w0.2: 72.823,41.323 72.823,40.903 72.873,40.853 D11.2@72.898,40.828
  Top Layer w0.3: v1@68.453,38.748 71.28,41.575 71.711,41.575 71.714,41.578 72.568,41.578 72.823,41.323 72.873,41.273 D11.2@72.873,40.853
  Top Layer w0.4: C12.2@6.223,25.928 6.457,26.162 7.874,26.162 8.255,25.781 U1.8@8.255,24 U1.8@8.255,23.05 ; C3.2@10.668,6.299 C4.2@13.208,6.299 13.271,6.363 19.113,6.363 C5.2@19.177,6.426 C6.2@21.844,6.426 ; C10.1@20.828,66.243 C11.1@26.67,66.243 30.556,66.243 ; C19.1@30.48,19.482 29.084,19.482 26.823,21.742 26.772,21.742 24.511,24.003 24.511,31.115 25.019,31.623 28.181,31.623 30.416,29.388 C18.2@30.607,29.388 31.953,29.388 33.604,27.737 C17.1@35.052,27.737 35.103,27.686 37.276,27.686 37.361,27.771 37.692,27.771 40.936,27.771 41.284,27.423 ; v1(33.807,75.184) 33.63,75.006 C13.2@31.115,75.006 29.098,75.006 28.448,74.356 U2.7@28.448,73.038 28.448,72.456 30.861,70.043 30.861,66.548 30.556,66.243 ; v1(38.354,79.756) 49.011,79.756 C29.2@49.265,79.502 ; U4.5@38.842,26.171 41.05,26.171 41.284,26.405 41.284,27.423 ; U5.7@40.132,66.98 40.085,66.933 40.085,66.02 39.851,65.786 38.1,65.786 37.592,66.294 C22.2@37.592,67.31 37.401,67.31 36.335,66.243 30.556,66.243 ; U9.5@49.53,82.169 49.482,82.121 49.482,80.978 49.276,80.772 49.276,79.513 C29.2@49.265,79.502 ; U9.4@49.53,87.769 U9.3@50.8,87.769 ; C26.1@53.34,78.094 49.499,78.094 49.265,78.328 C29.2@49.265,79.502 ; ISCP.6@54.991,25.527 53.8,26.718 51.432,26.718 C14.2@51.308,26.594 51.117,26.594 50.74,26.971 45.261,26.971 44.822,27.41 41.297,27.41 41.284,27.423 ; C25.1@64.841,35.136 68.453,38.748 v1(68.453,38.862) ; v1(67.564,24.638) 66.167,24.638 64.761,23.232 64.57,23.232 64.262,22.924 C16.1@64.262,22.733 C15.1@70.561,22.733 ; v2(69.469,48.514) 70.105,48.514 R29.1@70.359,48.768 ; U3.1@78.74,14.252 78.74,15.514 78.974,15.748 82.169,15.748 84.582,13.335 84.582,8.382 ; v1(79.629,41.529) 83.439,41.529 87.463,45.553 C24.2@87.463,47.371
  Top Layer w0.8: C6.2@21.844,6.426 22.034,6.426 23.914,4.547 ; C26.1@53.34,78.094 53.351,78.105 pad.14@55.639,78.105 57.353,79.819 C21.2@57.353,80.01 ; 53.912,63.881 53.912,66.421 ; U6.2@77.928,57.144 U6.2@78.442,57.658 ; C8.2@81.788,9.068 C7.2@81.788,11.176 81.978,11.176 82.086,11.068 82.086,10.878 84.582,8.382 84.582,1.905 ; R30.2@92.53,70.231 92.53,72.889 93.216,73.575 POWER.0@93.216,74.17
  Top Layer w1: R12.1@4.19,25.781 4.191,26.797 5.461,28.067 Encoder.1@5.461,32.512 ; R12.1@4.192,25.654 4.387,25.459 6.215,25.459 C12.2@6.223,25.451 ; D1.3@5.527,42.278 5.527,44.008 v1(6.985,45.466) ; C3.2@10.668,6.299 10.66,6.307 9.06,6.307 ; D3.3@11.364,42.405 11.364,45.405 11.303,45.466 ; 14.407,43.759 14.407,40.953 14.414,40.945 C1.2@14.605,40.945 ; 14.451,43.804 12.789,45.466 11.303,45.466 ; 23.914,4.547 23.812,4.445 10.922,4.445 9.06,6.307 ; 24.106,4.469 S2.4@28.731,4.469 S2.1@35.131,4.469 S3.4@40.351,4.469 S3.1@46.752,4.469 RST.4@51.972,4.469 RST.1@58.372,4.469 58.372,2.491 59.339,1.524 85.995,1.524 USB.MH@94.961,10.49 ; C18.2@30.607,29.388 v1(30.607,32.131) ; R27.2@48.054,97.028 R27.2@48.054,96.012 ; U9.4@49.53,87.769 49.01,87.769 48.054,88.725 R28.2@48.054,91.311 ; D2.3@49.644,42.357 49.824,42.357 51.491,40.69 51.491,40.648 51.498,40.64 C2.2@51.689,40.64 51.88,40.64 51.887,40.648 51.887,40.838 52.705,41.656 Encoder.1@55.214,41.656 ; R24.2@52.069,66.802 52.094,66.777 52.094,66.705 53.628,66.705 53.912,66.421 ; R24.2@52.069,66.802 R23.2@52.07,68.834 ; 53.912,63.881 53.912,62.166 57.531,58.547 63.678,58.547 ; Encoder.6@59.214,43.656 59.214,45.007 59.8,45.593 64.311,45.593 64.897,46.179 64.897,52.504 65.483,53.09 66.171,53.09 C31.2@66.421,53.34 66.421,57.332 66.345,57.408 C32.2@66.345,57.658 66.345,57.908 66.095,57.908 65.456,58.547 63.678,58.547 ; C25.1@64.643,35.128 64.651,35.136 64.841,35.136 66.491,35.136 67.273,35.918 D10.A@70.098,35.918 ; 68.486,65.186 68.484,65.188 68.453,65.151 68.453,68.707 69.342,69.596 U7.4@69.342,72.517 ; 69.104,63.619 66.794,63.619 63.678,60.503 63.678,58.547 ; U7.4@69.471,72.388 U7.4@69.342,72.517 ; 72.468,69.215 71.882,69.801 U7.5@71.882,72.517 ; Encoder.1@5.461,32.512 1.27,28.321 1.27,14.097 9.06,6.307 ; Encoder.1@5.461,32.512 Encoder.2@5.461,35.052 2.159,38.354 2.159,44.831 2.794,45.466 v1(6.985,45.466) ; v1(6.985,45.466) 11.303,45.466 ; R28.2@48.054,91.311 R28.2@48.054,91.313 R27.2@48.054,96.012 ; R28.2@48.054,91.311 48.179,91.186 v1(49.403,91.186) 49.403,91.259 49.53,91.386 v1(49.53,92.888) v1(49.53,94.437) v1(49.53,96.012) R27.2@48.054,96.012 ; U7.4@69.342,72.517 U7.13@69.342,80.137 U7.12@71.882,80.137 v2(71.882,77.216) U7.5@71.882,72.517 ; U7.4@69.342,72.517 U7.5@71.882,72.517
  Bottom Layer w0.2: U8.19@68.453,34.069 U8.19@68.453,35.052
  Bottom Layer w0.4: Encoder.1@11.049,70.866 16.764,70.866 21.082,75.184 v1(33.807,75.184) 38.354,79.731 v1(38.354,79.756) ; v1(67.564,24.638) 69.85,22.352 94.783,22.352 USB.MH@94.961,22.53 ; U8.19@68.453,35.052 v1(68.453,38.862) 67.194,40.121 67.194,44.591 U8.1@67.183,44.602 67.194,44.613 67.194,46.623 67.176,46.641 67.176,47.974 67.85,48.648 78.581,48.648 79.255,47.974 79.255,44.602 U8.10@78.613,44.602 78.613,42.545 v1(79.629,41.529)
  Bottom Layer w0.8: U7.13@69.342,79.475 U7.13@69.342,80.137
  Bottom Layer w1: v1(6.985,45.466) v1@7.023,45.504 ; v1(30.607,32.131) 30.607,33.147 29.845,33.909 25.654,33.909 18.034,41.529 18.034,53.213 22.391,57.57 65.239,57.57 66.345,56.464 ; 47.625,97.409 50.546,97.409 50.681,97.544 ; Encoder.1@55.214,41.656 52.603,41.656 51.284,42.975 51.284,44.591 52.551,45.858 57.113,45.858 59.214,43.757 Encoder.6@59.214,43.656 ; C32.2@66.345,57.658 66.345,56.464 ; C24.2@87.463,47.371 87.503,47.411 87.503,49.022 85.217,51.308 71.325,51.308 70.739,51.894 70.739,52.07 66.802,56.007 66.345,56.464 ; D4.3@89.723,9.411 93.071,9.411 94.15,10.49 USB.MH@94.961,10.49 94.996,10.525 94.996,22.495 USB.MH@94.961,22.53 ; USB.4@92.252,17.76 94.387,19.896 94.387,21.956 USB.MH@94.783,22.352
  other v2: 69.215,77.216
1A: C10.2 D2.2 Encoder.2@8.509,70.866 Encoder.5@59.214,41.656 R15.1 R19.1 U2.1 | length 104.3
  Top Layer w0.4: Encoder.2@8.509,70.866 8.509,69.215 9.601,68.123 C10.2@20.828,68.123 20.955,68.25 R19.1@20.955,70.104 20.892,70.168 20.892,73.343 20.828,73.406 20.828,75.692 19.685,76.835 R15.1@13.589,76.835 ; v1(24.892,62.738) 27.94,62.738 29.337,64.135 31.115,64.135 36.322,58.928 38.862,58.928 42.669,55.121 42.669,42.929 44.191,41.407 D2.2@47.244,41.407 47.244,40.621 47.305,40.56 47.539,40.56 47.839,40.259 v1(49.276,40.259)
  Bottom Layer w0.4: Encoder.2@8.509,70.866 8.763,70.612 8.763,68.961 15.24,62.484 24.422,62.484 24.676,62.738 v1(24.892,62.738) ; v1(49.276,40.259) 58.864,40.259 59.214,40.609 Encoder.5@59.214,41.656
2: D1.2 Encoder.3@8.001,32.512 Encoder.4@8.001,35.052 R4.1 | length 32.4
  Top Layer w0.8: v1(6.35,14.224) 6.35,13.208 7.366,12.192 8.942,12.192 R4.1@9.017,12.192
  Top Layer w1: D1.2@4.577,39.878 4.677,39.778 4.677,38.376 Encoder.4@8.001,35.052 Encoder.3@8.001,32.512
  Bottom Layer w0.8: v1(6.35,14.224) 5.715,14.859 5.715,28.448 8.001,30.734 Encoder.3@8.001,32.512
2A: C11.2 D2.1 Encoder.3@5.969,70.866 Encoder.4@57.214,43.656 R11.1 R20.1 U2.3 | length 102.9
  Top Layer w0.4: v1@17.399,74.168 17.399,74.422 12.7,74.422 11.469,75.653 11.469,78.906 12.826,80.263 R11.1@17.653,80.263 ; v1(22.606,76.708) 23.268,76.046 23.268,73.506 23.368,73.406 U2.3@23.368,73.038 23.368,71.315 24.579,70.104 26.416,70.104 26.416,68.377 26.379,68.414 24.804,68.414 v1(24.638,68.58) ; v1(25.019,64.77) 31.369,64.77 35.56,60.579 38.1,60.579 43.219,55.46 43.219,44.284 44.196,43.307 D2.1@47.244,43.307 47.624,43.307 48.224,43.907 51.519,43.907 51.935,43.491 v1(52.889,43.491) ; Encoder.4@57.152,43.718 Encoder.4@57.214,43.656
  Bottom Layer w0.4: Encoder.3@5.969,70.866 6.061,70.958 6.061,72.355 8.128,74.422 v1(17.653,74.422) 19.939,76.708 v1(22.606,76.708) ; v1(24.638,68.58) 24.638,68.364 25.019,67.983 v1(25.019,64.77) ; v1(52.889,43.491) 52.946,43.548 52.946,43.929 53.975,44.958 55.912,44.958 Encoder.4@57.214,43.656
3: D1.1 Encoder.5@10.541,32.512 Encoder.6@10.541,35.052 R5.1 | length 32.1
  Top Layer w0.4: R5.1@14.859,12.192 14.859,12.367 15.875,13.383 v1(15.875,16.383)
  Top Layer w1: D1.1@6.477,39.878 6.477,39.698 9.398,36.777 9.398,36.33 10.541,35.187 Encoder.6@10.541,35.052 Encoder.5@10.541,32.512
  Bottom Layer w0.4: Encoder.5@10.541,32.512 10.541,29.823 12.481,27.883 12.481,19.65 15.748,16.383 v1(15.875,16.383)
4: D3.2 Encoder.7@13.081,32.512 Encoder.8@13.081,35.052 R6.1 | length 31
  Top Layer w0.4: R6.1@17.527,12.192 17.654,12.318 17.654,13.971 v1(17.78,14.097)
  Top Layer w1: D3.2@10.414,40.005 10.414,37.719 Encoder.8@13.081,35.052 Encoder.7@13.081,32.512
  Bottom Layer w0.4: Encoder.7@13.081,32.512 13.081,26.797 14.859,25.019 14.859,19.394 17.78,16.473 v1(17.78,14.097)
5: D3.1 Encoder.9@15.621,32.512 Encoder.10@15.621,35.052 R7.2 | length 32.4
  Top Layer w0.4: v1(22.86,16.129) 23.495,15.494 R7.2@23.495,12.192
  Top Layer w1: D3.1@12.314,40.005 12.414,39.905 12.414,38.513 12.446,38.481 12.446,38.362 15.621,35.187 Encoder.10@15.621,35.052 Encoder.9@15.621,32.512
  Bottom Layer w0.4: Encoder.9@15.621,32.512 22.86,25.273 v1(22.86,16.129)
